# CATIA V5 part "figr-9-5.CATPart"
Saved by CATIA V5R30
Part number: Part1
Bounding box of the stored display mesh (mm): x -71.324 to 69.61, y -211.059 to 0, z 0 to 45
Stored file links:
  D:\PROJECTS\CATIA V56R 2020\Resources\Parts File\c09_catia_v5_6r2020_prt\figr-9-5.CATPart
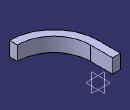
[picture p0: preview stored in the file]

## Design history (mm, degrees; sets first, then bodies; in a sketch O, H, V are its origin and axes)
Body1 (main body)
  Sketch1 on xy-plane, origin (0, 0, 0), H (1, 0, 0), V (0, 1, 0)
    line L1 (0, 0) -> (0, -70.1255)
    arc A1 centre (69.6095, -70.1255) radius 69.6095 from (0, -70.1255) to (69.6095, -139.7351) ccw
    vertical: L1 V
    tangency: A1 L1
  Sketch2 on zx-plane, origin (0, 0, 0), H (-1, 0, 0), V (0, 0, 1)
    point P1 (46.3244, 0)
    line L1 (46.3244, 0) -> (71.3244, 0)
    line L2 (71.3244, 0) -> (71.3244, 45)
    line L3 (71.3244, 45) -> (46.3244, 45)
    line L4 (46.3244, 45) -> (46.3244, 0)
    length L3 = 25
    length L2 = 45
    coincidence: P1 H
    horizontal: L1 H, L3 H
    vertical: L2 V, L4 V
  Rib1: profile Sketch2, centre curve Sketch1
